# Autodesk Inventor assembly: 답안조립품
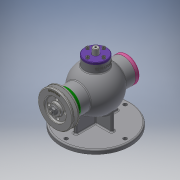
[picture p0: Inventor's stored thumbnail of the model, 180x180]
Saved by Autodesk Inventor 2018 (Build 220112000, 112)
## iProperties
Created: 2020-08
Part Number: 답안조립품
Material: 일반
Document SubType Name: Assembly
Designer: USER
Author: USER
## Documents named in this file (18)
- C:\Users\USER\Desktop\700806V1006\답안조립품.iam
- C:\Users\USER\Desktop\700806V1006\본체.ipt
- C:\Users\USER\Desktop\700806V1006\Ű 3x3x12.ipt
- C:\Users\USER\Desktop\700806V1006\V-벨트풀리.ipt
- C:\Users\USER\Desktop\700806V1006\너트 M8.ipt
- C:\Users\USER\Desktop\700806V1006\뒤커버.ipt
- C:\Users\USER\Desktop\700806V1006\멈춤링 15x1.ipt
- C:\Users\USER\Desktop\700806V1006\멈춤링 35x1.6.ipt
- 멈춤링 35x1.6.ipt
- C:\Users\USER\Desktop\700806V1006\베어링 6202.ipt
- 베어링 6202.ipt
- C:\Users\USER\Desktop\700806V1006\볼트 M4.ipt
- C:\Users\USER\Desktop\700806V1006\상부커버.ipt
- C:\Users\USER\Desktop\700806V1006\슬라이드.ipt
- C:\Users\USER\Desktop\700806V1006\앞커버.ipt
- C:\Users\USER\Desktop\700806V1006\오일 실 15 30 7.ipt
- C:\Users\USER\Desktop\700806V1006\칼라.ipt
- C:\Users\USER\Desktop\700806V1006\편심축.ipt
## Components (2 placed, 2 different names)
1. Ű 3x3x12:1
2. V-벨트풀리:1
